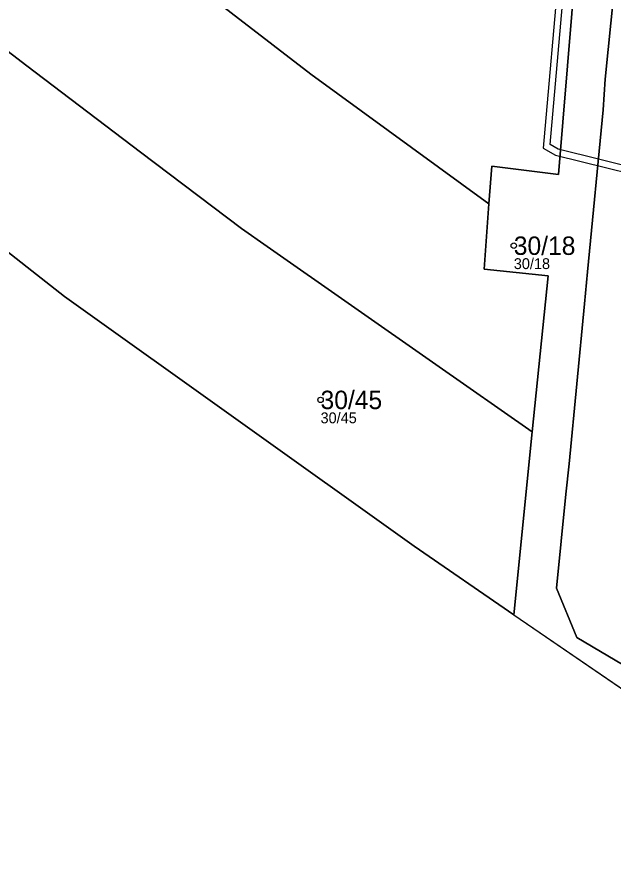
# Model space of a CAD drawing. Extents: x -734965 to -732523, y -1026217 to -1023680.
# Drawn here: x -733589.2 to -733534.1, y -1026071.7 to -1025993.8 of the extents above; entities that cross this region are included whole.
import ezdxf

# ---------------------------------------------------------------- set-up
doc = ezdxf.new("R2010")
doc.units = 0
for name, color, linetype in [('Vrstva 1', 7, 'Continuous'), ('Vrstva 13', 7, 'Continuous'), ('Vrstva 2', 7, 'Continuous'), ('Vrstva 50', 7, 'Continuous'), ('Vrstva 51', 7, 'Continuous'), ('Vrstva 53', 7, 'Continuous')]:
    doc.layers.add(name, color=color, linetype=linetype)

msp = doc.modelspace()

# ---------------------------------------------------------------- linework, layer by layer
at = {"layer": 'Vrstva 1'}
for p, q in [((-733541.6, -1026032.07), (-733543.3, -1026048.94)), ((-733543.3, -1026048.94), (-733530.04, -1026058.02))]:
    msp.add_line(p, q, dxfattribs=at)
for points in [[(-733534.81, -1025957.77), (-733536.9, -1025981.88), (-733537.12, -1025983.39), (-733539.17, -1026008.33), (-733545.34, -1026007.54), (-733545.6, -1026011.02)], [(-733605.09, -1025963.8), (-733603.57, -1025965.12), (-733602.49, -1025966.05), (-733583.71, -1025982.36), (-733562.03, -1025999.05), (-733545.6, -1026011.02)], [(-733615.43, -1025975.86), (-733613.91, -1025977.14), (-733612.79, -1025978.09), (-733596.12, -1025992.13), (-733595.53, -1025992.63), (-733593.94, -1025993.96), (-733593.18, -1025994.54), (-733588.25, -1025998.28), (-733577.75, -1026006.25), (-733568.44, -1026013.31), (-733566.08, -1026014.96), (-733550.51, -1026025.86), (-733541.6, -1026032.07)], [(-733492.28, -1025987.66), (-733497.58, -1026006.91), (-733498.03, -1026009.35), (-733501.98, -1026024.43), (-733502.53, -1026026.91), (-733505.32, -1026042.22), (-733505.74, -1026044.69), (-733508.08, -1026065.46), (-733510.89, -1026066.76), (-733537.47, -1026051.06), (-733539.37, -1026046.5), (-733538.49, -1026037.82), (-733538.19, -1026035.03), (-733536.78, -1026020.26), (-733536.5, -1026017.3), (-733535.05, -1026002.36), (-733534.86, -1025999.51), (-733533.27, -1025983.68)], [(-733543.3, -1026048.94), (-733552.5, -1026042.63), (-733584.77, -1026019.57), (-733599.76, -1026007.82)], [(-733545.6, -1026011.02), (-733546.04, -1026017.06), (-733540.14, -1026017.66), (-733541.6, -1026032.07)]]:
    msp.add_lwpolyline(points, dxfattribs=at)
at = {"layer": 'Vrstva 13'}
msp.add_lwpolyline([(-733539.09, -1025988.77), (-733540.58, -1026005.89), (-733539.44, -1026006.55), (-733527.71, -1026009.44), (-733527.65, -1026008.84), (-733539.21, -1026005.99), (-733539.95, -1026005.56), (-733538.48, -1025988.73)], dxfattribs=at)
at = {"layer": 'Vrstva 50'}
for centre in [(-733543.3, -1026014.89), (-733561.14, -1026029.12)]:
    msp.add_circle(centre, 0.25, dxfattribs=at)
at = {"layer": 'Vrstva 51'}
for points in [[(-733602.49, -1025966.05), (-733583.71, -1025982.36), (-733562.03, -1025999.05), (-733545.6, -1026011.02), (-733545.34, -1026007.54), (-733539.17, -1026008.33), (-733537.12, -1025983.39), (-733536.9, -1025981.88), (-733534.81, -1025957.77), (-733551.33, -1025943.23), (-733561.61, -1025934.18), (-733581.11, -1025917.49)], [(-733492.28, -1025987.66), (-733497.58, -1026006.91), (-733498.03, -1026009.35), (-733501.98, -1026024.43), (-733502.53, -1026026.91), (-733505.32, -1026042.22), (-733505.74, -1026044.69), (-733508.08, -1026065.46), (-733510.89, -1026066.76), (-733537.47, -1026051.06), (-733539.37, -1026046.5), (-733538.49, -1026037.82), (-733538.19, -1026035.03), (-733536.78, -1026020.26), (-733536.5, -1026017.3), (-733535.05, -1026002.36), (-733534.86, -1025999.51), (-733533.27, -1025983.68)], [(-733533.27, -1025983.68), (-733534.86, -1025999.51), (-733535.05, -1026002.36), (-733536.5, -1026017.3), (-733536.78, -1026020.26), (-733538.19, -1026035.03), (-733538.49, -1026037.82), (-733539.37, -1026046.5), (-733537.47, -1026051.06), (-733510.89, -1026066.76), (-733508.08, -1026065.46), (-733505.74, -1026044.69), (-733505.32, -1026042.22), (-733502.53, -1026026.91), (-733501.98, -1026024.43), (-733498.03, -1026009.35), (-733497.58, -1026006.91), (-733492.28, -1025987.66)], [(-733599.76, -1026007.82), (-733584.77, -1026019.57), (-733552.5, -1026042.63), (-733543.3, -1026048.94), (-733541.6, -1026032.07), (-733550.51, -1026025.86), (-733566.08, -1026014.96), (-733568.44, -1026013.31), (-733577.75, -1026006.25), (-733588.25, -1025998.28), (-733593.18, -1025994.54)]]:
    msp.add_lwpolyline(points, dxfattribs=at)
for points in [[(-733545.34, -1026007.54), (-733545.6, -1026011.02), (-733546.04, -1026017.06), (-733540.14, -1026017.66), (-733541.6, -1026032.07), (-733543.3, -1026048.94), (-733530.04, -1026058.02), (-733508.23, -1026071.1), (-733505.96, -1026071.59), (-733505.55, -1026071.68), (-733502.66, -1026044.81), (-733496.93, -1026016.32), (-733495.22, -1026010.4), (-733489.35, -1025989.4), (-733489.87, -1025986.38), (-733490.38, -1025983.42), (-733494.21, -1025977.19), (-733534.51, -1025951.22), (-733534.56, -1025954.85), (-733534.81, -1025957.77), (-733536.9, -1025981.88), (-733537.12, -1025983.39), (-733539.17, -1026008.33)], [(-733577.75, -1026006.25), (-733568.44, -1026013.31), (-733566.08, -1026014.96), (-733550.51, -1026025.86), (-733541.6, -1026032.07), (-733540.14, -1026017.66), (-733546.04, -1026017.06), (-733545.6, -1026011.02), (-733562.03, -1025999.05), (-733583.71, -1025982.36), (-733602.49, -1025966.05), (-733603.57, -1025965.12), (-733605.09, -1025963.8), (-733615.43, -1025975.86), (-733613.91, -1025977.14), (-733612.79, -1025978.09), (-733596.12, -1025992.13), (-733595.53, -1025992.63), (-733593.94, -1025993.96), (-733593.18, -1025994.54), (-733588.25, -1025998.28)]]:
    msp.add_lwpolyline(points, close=True, dxfattribs=at)
at = {"layer": 'Vrstva 53'}
msp.add_lwpolyline([(-733599.76, -1026007.82), (-733584.77, -1026019.57), (-733552.5, -1026042.63), (-733543.3, -1026048.94), (-733530.04, -1026058.02)], dxfattribs=at)

# ---------------------------------------------------------------- texts
at = {"layer": 'Vrstva 2'}
for s, p in [('30/18', (-733543.3, -1026015.74)), ('30/45', (-733561.14, -1026029.97))]:
    msp.add_text(s, height=1.7, dxfattribs=at).set_placement(p)
at = {"layer": 'Vrstva 50'}
for s, p in [('30/18', (-733543.3, -1026017.046)), ('30/45', (-733561.14, -1026031.276))]:
    msp.add_text(s, height=1, dxfattribs=at).set_placement(p)

doc.saveas('drawing.dxf')
